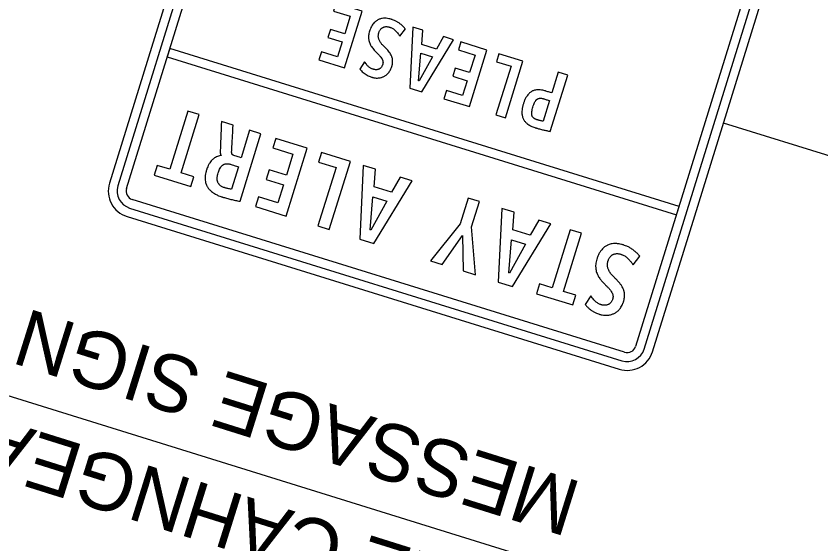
# Model space of a CAD drawing. Extents: x 2135767 to 2151731, y 141839 to 175894.
# Drawn here: x 2151050.4 to 2151135.3, y 149117.3 to 149173 of the extents above; entities that cross this region are included whole.
import ezdxf

# ---------------------------------------------------------------- set-up
doc = ezdxf.new("R2010")
doc.units = 0
for name, color, linetype in [('PR_Dimensions_Phase', 7, 'Continuous'), ('PR_Traffic_Control_Devices_Temp', 7, 'Continuous'), ('PR_Txt', 7, 'Continuous')]:
    doc.layers.add(name, color=color, linetype=linetype)

msp = doc.modelspace()

# ---------------------------------------------------------------- linework, layer by layer
at = {"layer": 'PR_Dimensions_Phase'}
for p, q in [((2151325.291, 149099.595), (2151125.02, 149161.695)), ((2151310.484, 149051.853), (2151016.595, 149143.158))]:
    msp.add_line(p, q, dxfattribs=at)
at = {"layer": 'PR_Traffic_Control_Devices_Temp'}
for p, q in [((2151090.863, 149170.866), (2151091.446, 149171.627)), ((2151087.144, 149168.154), (2151086.651, 149167.385)), ((2151106.656, 149164.065), (2151105.981, 149161.889)), ((2151073.274, 149161.472), (2151072.029, 149161.858)), ((2151072.014, 149158.28), (2151072.01, 149158.266)), ((2151073.822, 149157.085), (2151073.085, 149154.709)), ((2151115.495, 149146.724), (2151116.194, 149147.637)), ((2151111.032, 149143.47), (2151110.44, 149142.547))]:
    msp.add_line(p, q, dxfattribs=at)
for points in [[(2151076.329, 149207.298), (2151064.664, 149169.678), (2151060.221, 149155.351)], [(2151077.225, 149207.02), (2151061.116, 149155.073)], [(2151062.012, 149154.795), (2151078.12, 149206.743)], [(2151131.858, 149190.079), (2151115.75, 149138.132)], [(2151116.645, 149137.854), (2151132.754, 149189.801)], [(2151117.541, 149137.576), (2151121.983, 149151.903), (2151133.649, 149189.524)], [(2151084.294, 149168.677), (2151082.596, 149169.204), (2151082.331, 149168.348), (2151085.022, 149167.513), (2151086.873, 149173.483), (2151084.123, 149174.336), (2151083.864, 149173.502), (2151085.621, 149172.957), (2151085.047, 149171.107), (2151083.531, 149171.577), (2151083.266, 149170.722), (2151084.782, 149170.251), (2151084.294, 149168.677)], [(2151096.531, 149170.488), (2151095.487, 149170.812), (2151094.718, 149169.492), (2151093.203, 149169.962), (2151093.304, 149171.489), (2151092.23, 149171.822), (2151091.914, 149165.36), (2151093.172, 149164.97), (2151096.531, 149170.488)], [(2151097.969, 149166.162), (2151097.48, 149164.588), (2151095.783, 149165.115), (2151095.518, 149164.259), (2151098.209, 149163.424), (2151100.06, 149169.394), (2151097.31, 149170.247), (2151097.051, 149169.413), (2151098.807, 149168.868), (2151098.234, 149167.018), (2151096.718, 149167.488), (2151096.453, 149166.632), (2151097.969, 149166.162)], [(2151093.075, 149169.063), (2151094.298, 149168.684), (2151092.896, 149166.145), (2151092.836, 149166.164), (2151093.075, 149169.063)], [(2151103.857, 149168.217), (2151101.318, 149169.004), (2151101.057, 149168.162), (2151102.602, 149167.683), (2151101.012, 149162.555), (2151102.005, 149162.247), (2151103.857, 149168.217)], [(2151106.737, 149160.814), (2151108.578, 149166.752), (2151107.585, 149167.061), (2151106.905, 149164.87)], [(2151069.69, 149162.583), (2151068.498, 149162.953), (2151066.595, 149156.816), (2151065.27, 149157.227), (2151064.952, 149156.2), (2151068.793, 149155.009), (2151069.112, 149156.036), (2151067.787, 149156.447), (2151069.69, 149162.583)], [(2151073.998, 149153.437), (2151076.207, 149160.562), (2151075.015, 149160.932), (2151074.119, 149158.042)], [(2151081.086, 149159.049), (2151077.785, 149160.073), (2151077.475, 149159.072), (2151079.583, 149158.418), (2151078.895, 149156.199), (2151077.076, 149156.763), (2151076.757, 149155.736), (2151078.576, 149155.172), (2151077.99, 149153.283), (2151075.954, 149153.914), (2151075.635, 149152.887), (2151078.864, 149151.886), (2151081.086, 149159.049)], [(2151082.228, 149150.843), (2151083.42, 149150.473), (2151085.642, 149157.637), (2151082.595, 149158.581), (2151082.282, 149157.572), (2151084.136, 149156.997), (2151082.228, 149150.843)], [(2151092.167, 149155.613), (2151090.914, 149156.002), (2151089.991, 149154.418), (2151088.173, 149154.982), (2151088.294, 149156.814), (2151087.006, 149157.214), (2151086.626, 149149.46), (2151088.136, 149148.992), (2151092.167, 149155.613)], [(2151114.577, 149137.514), (2151062.63, 149153.622)], [(2151088.019, 149153.904), (2151089.487, 149153.448), (2151087.805, 149150.402), (2151087.733, 149150.424), (2151088.019, 149153.904)], [(2151097.496, 149149.815), (2151097.563, 149146.088), (2151098.837, 149145.693), (2151098.438, 149150.732), (2151099.269, 149153.411), (2151098.076, 149153.781), (2151097.23, 149151.052), (2151094.108, 149147.159), (2151095.332, 149146.78), (2151097.496, 149149.815)], [(2151062.352, 149152.727), (2151114.299, 149136.619)], [(2151106.795, 149151.077), (2151105.542, 149151.466), (2151104.619, 149149.882), (2151102.801, 149150.446), (2151102.922, 149152.278), (2151101.633, 149152.678), (2151101.254, 149144.924), (2151102.764, 149144.456), (2151106.795, 149151.077)], [(2151062.074, 149151.831), (2151114.021, 149135.723)], [(2151110.028, 149150.075), (2151108.835, 149150.445), (2151106.933, 149144.308), (2151105.608, 149144.719), (2151105.29, 149143.692), (2151109.131, 149142.501), (2151109.45, 149143.528), (2151108.125, 149143.938), (2151110.028, 149150.075)], [(2151102.647, 149149.368), (2151104.115, 149148.913), (2151102.432, 149145.866), (2151102.361, 149145.888), (2151102.647, 149149.368)]]:
    msp.add_lwpolyline(points, dxfattribs=at)
msp.add_lwpolyline([(2151120.054, 149152.011), (2151120.331, 149152.907), (2151066.593, 149169.57), (2151066.316, 149168.675)], close=True, dxfattribs=at)
msp.add_lwpolyline([(2151120.054, 149152.011), (2151120.331, 149152.907), (2151066.593, 149169.57), (2151066.316, 149168.675)], close=True, dxfattribs=at)
for centre, radius, start, end in [((2151062.907, 149154.518), 2.812, 162.77193, 252.77193), ((2151062.907, 149154.518), 1.875, 162.77193, 252.77193), ((2151062.907, 149154.518), 0.937, 162.77193, 252.77193), ((2151114.854, 149138.409), 0.937, 252.77193, 342.77193), ((2151114.854, 149138.409), 2.812, 252.77193, 342.77193), ((2151114.854, 149138.409), 1.875, 252.77193, 342.77193)]:
    msp.add_arc(centre, radius, start, end, dxfattribs=at)
for points in [[(2151091.446, 149171.627), (2151091.399, 149171.682), (2151091.259, 149171.846), (2151091.047, 149172.043), (2151090.82, 149172.223), (2151090.573, 149172.389), (2151090.297, 149172.525), (2151090.078, 149172.599), (2151090.002, 149172.624), (2151089.929, 149172.645), (2151089.722, 149172.705), (2151089.414, 149172.752), (2151089.12, 149172.748), (2151088.91, 149172.715), (2151088.741, 149172.667), (2151088.609, 149172.61), (2151088.508, 149172.555), (2151088.411, 149172.494), (2151088.296, 149172.408), (2151088.169, 149172.29), (2151088.032, 149172.133), (2151087.874, 149171.899), (2151087.749, 149171.633), (2151087.687, 149171.441), (2151087.665, 149171.374)], [(2151086.651, 149167.385), (2151086.692, 149167.336), (2151086.814, 149167.191), (2151086.997, 149167.018), (2151087.193, 149166.868), (2151087.406, 149166.731), (2151087.643, 149166.619), (2151087.832, 149166.556), (2151087.898, 149166.534), (2151087.956, 149166.518), (2151088.123, 149166.47), (2151088.378, 149166.437), (2151088.628, 149166.446), (2151088.815, 149166.477), (2151088.945, 149166.513), (2151089.072, 149166.56), (2151089.173, 149166.605), (2151089.293, 149166.67), (2151089.407, 149166.744), (2151089.533, 149166.846), (2151089.648, 149166.961), (2151089.733, 149167.067), (2151089.843, 149167.229), (2151089.937, 149167.412), (2151089.993, 149167.578), (2151090.012, 149167.636), (2151090.025, 149167.678), (2151090.06, 149167.8), (2151090.097, 149168.003), (2151090.109, 149168.243), (2151090.089, 149168.437), (2151090.061, 149168.569), (2151090.039, 149168.644), (2151089.998, 149168.764), (2151089.904, 149168.954), (2151089.763, 149169.159), (2151089.583, 149169.383), (2151089.455, 149169.516), (2151089.368, 149169.607), (2151089.152, 149169.819), (2151088.922, 149170.045), (2151088.734, 149170.347), (2151088.68, 149170.46), (2151088.634, 149170.595), (2151088.607, 149170.717), (2151088.594, 149170.808), (2151088.591, 149170.905), (2151088.601, 149171.005), (2151088.62, 149171.11), (2151088.638, 149171.174), (2151088.65, 149171.218), (2151088.661, 149171.25), (2151088.692, 149171.342), (2151088.755, 149171.47), (2151088.834, 149171.581), (2151088.903, 149171.655), (2151088.968, 149171.71), (2151089.026, 149171.749), (2151089.075, 149171.777), (2151089.126, 149171.802), (2151089.191, 149171.828), (2151089.273, 149171.85), (2151089.373, 149171.865), (2151089.51, 149171.868), (2151089.65, 149171.848), (2151089.744, 149171.821), (2151089.776, 149171.811), (2151089.807, 149171.801), (2151089.896, 149171.772), (2151090.038, 149171.709), (2151090.196, 149171.615), (2151090.316, 149171.521), (2151090.425, 149171.417), (2151090.529, 149171.305), (2151090.688, 149171.119), (2151090.793, 149170.967), (2151090.863, 149170.866)], [(2151087.665, 149171.374), (2151087.645, 149171.305), (2151087.599, 149171.144), (2151087.563, 149170.918), (2151087.556, 149170.733), (2151087.565, 149170.59), (2151087.59, 149170.405), (2151087.642, 149170.2), (2151087.721, 149170.012), (2151087.812, 149169.835), (2151087.92, 149169.67), (2151088.075, 149169.483), (2151088.236, 149169.306), (2151088.368, 149169.169), (2151088.432, 149169.102), (2151088.497, 149169.039), (2151088.687, 149168.854), (2151088.881, 149168.633), (2151088.998, 149168.438), (2151089.037, 149168.36), (2151089.065, 149168.28), (2151089.082, 149168.2), (2151089.09, 149168.131), (2151089.09, 149168.062), (2151089.084, 149168.004), (2151089.073, 149167.946), (2151089.063, 149167.911), (2151089.057, 149167.888), (2151089.047, 149167.857), (2151089.014, 149167.758), (2151088.953, 149167.639), (2151088.876, 149167.541), (2151088.822, 149167.485), (2151088.763, 149167.438), (2151088.71, 149167.406), (2151088.654, 149167.379), (2151088.574, 149167.348), (2151088.452, 149167.32), (2151088.299, 149167.316), (2151088.169, 149167.335), (2151088.091, 149167.357), (2151088.064, 149167.365), (2151088.039, 149167.374), (2151087.964, 149167.398), (2151087.846, 149167.449), (2151087.715, 149167.523), (2151087.616, 149167.595), (2151087.525, 149167.677), (2151087.4, 149167.806), (2151087.266, 149167.971), (2151087.176, 149168.107), (2151087.144, 149168.154)], [(2151106.905, 149164.87), (2151106.691, 149164.937), (2151106.476, 149165.003), (2151106.261, 149165.07), (2151106.187, 149165.091), (2151105.978, 149165.152), (2151105.668, 149165.203), (2151105.373, 149165.204), (2151105.165, 149165.175), (2151104.999, 149165.13), (2151104.87, 149165.077), (2151104.773, 149165.025), (2151104.678, 149164.966), (2151104.565, 149164.879), (2151104.438, 149164.755), (2151104.299, 149164.583), (2151104.134, 149164.319), (2151103.998, 149164.014), (2151103.926, 149163.794), (2151103.9, 149163.715)], [(2151104.91, 149163.383), (2151104.94, 149163.477), (2151104.996, 149163.648), (2151105.086, 149163.864), (2151105.168, 149164.011), (2151105.237, 149164.103), (2151105.29, 149164.159), (2151105.335, 149164.197), (2151105.38, 149164.23), (2151105.441, 149164.264), (2151105.52, 149164.293), (2151105.591, 149164.307), (2151105.649, 149164.312), (2151105.712, 149164.314), (2151105.817, 149164.306), (2151105.948, 149164.282), (2151106.043, 149164.254), (2151106.084, 149164.242), (2151106.275, 149164.183), (2151106.465, 149164.124), (2151106.656, 149164.065)], [(2151103.9, 149163.715), (2151103.875, 149163.631), (2151103.806, 149163.394), (2151103.753, 149163.081), (2151103.745, 149162.818), (2151103.753, 149162.65), (2151103.774, 149162.492), (2151103.819, 149162.312), (2151103.874, 149162.172), (2151103.928, 149162.067), (2151103.988, 149161.967), (2151104.076, 149161.849), (2151104.201, 149161.718), (2151104.319, 149161.62), (2151104.45, 149161.528), (2151104.656, 149161.404), (2151104.917, 149161.286), (2151105.126, 149161.217), (2151105.199, 149161.193), (2151105.272, 149161.171), (2151105.412, 149161.128), (2151105.617, 149161.069), (2151105.812, 149161.017), (2151105.999, 149160.971), (2151106.182, 149160.928), (2151106.365, 149160.89), (2151106.55, 149160.853), (2151106.674, 149160.827), (2151106.737, 149160.814)], [(2151105.981, 149161.889), (2151105.926, 149161.901), (2151105.818, 149161.926), (2151105.659, 149161.958), (2151105.509, 149161.99), (2151105.413, 149162.018), (2151105.366, 149162.032), (2151105.329, 149162.044), (2151105.243, 149162.073), (2151105.131, 149162.123), (2151105.048, 149162.174), (2151105, 149162.21), (2151104.958, 149162.247), (2151104.91, 149162.297), (2151104.863, 149162.364), (2151104.833, 149162.425), (2151104.815, 149162.478), (2151104.799, 149162.533), (2151104.782, 149162.625), (2151104.779, 149162.74), (2151104.793, 149162.907), (2151104.833, 149163.119), (2151104.883, 149163.29), (2151104.91, 149163.383)], [(2151072.029, 149161.858), (2151071.991, 149160.801), (2151071.952, 149159.744), (2151071.914, 149158.687), (2151071.914, 149158.645), (2151071.914, 149158.563), (2151071.923, 149158.473), (2151071.934, 149158.409), (2151071.945, 149158.373), (2151071.961, 149158.341), (2151071.975, 149158.318), (2151071.99, 149158.301), (2151072.003, 149158.289), (2151072.011, 149158.282), (2151072.014, 149158.28)], [(2151074.119, 149158.042), (2151073.85, 149158.126), (2151073.581, 149158.209), (2151073.313, 149158.292), (2151073.301, 149158.296), (2151073.274, 149158.305), (2151073.24, 149158.322), (2151073.209, 149158.341), (2151073.188, 149158.36), (2151073.169, 149158.38), (2151073.154, 149158.403), (2151073.145, 149158.423), (2151073.138, 149158.445), (2151073.132, 149158.468), (2151073.119, 149158.538), (2151073.114, 149158.631), (2151073.116, 149158.714), (2151073.117, 149158.745), (2151073.169, 149159.654), (2151073.222, 149160.563), (2151073.274, 149161.472)], [(2151072.01, 149158.266), (2151071.967, 149158.26), (2151071.842, 149158.242), (2151071.638, 149158.184), (2151071.406, 149158.077), (2151071.227, 149157.956), (2151071.092, 149157.843), (2151070.957, 149157.71), (2151070.803, 149157.509), (2151070.644, 149157.223), (2151070.53, 149156.951), (2151070.473, 149156.775), (2151070.453, 149156.713), (2151070.429, 149156.627), (2151070.349, 149156.349), (2151070.302, 149155.984), (2151070.323, 149155.639), (2151070.361, 149155.429), (2151070.424, 149155.229), (2151070.496, 149155.071), (2151070.565, 149154.952), (2151070.642, 149154.836), (2151070.752, 149154.697), (2151070.878, 149154.569), (2151071.077, 149154.396), (2151071.381, 149154.193), (2151071.765, 149154.018), (2151072.017, 149153.935), (2151072.106, 149153.905), (2151072.188, 149153.88), (2151072.347, 149153.832), (2151072.584, 149153.764), (2151072.815, 149153.702), (2151073.043, 149153.642), (2151073.27, 149153.586), (2151073.503, 149153.535), (2151073.746, 149153.485), (2151073.912, 149153.453), (2151073.998, 149153.437)], [(2151071.692, 149156.43), (2151071.708, 149156.482), (2151071.755, 149156.626), (2151071.846, 149156.843), (2151071.964, 149157.046), (2151072.073, 149157.178), (2151072.15, 149157.247), (2151072.202, 149157.284), (2151072.255, 149157.317), (2151072.325, 149157.351), (2151072.415, 149157.38), (2151072.511, 149157.398), (2151072.594, 149157.403), (2151072.722, 149157.401), (2151072.857, 149157.381), (2151072.97, 149157.348), (2151073.01, 149157.336), (2151073.281, 149157.253), (2151073.551, 149157.169), (2151073.822, 149157.085)], [(2151073.085, 149154.709), (2151073.023, 149154.718), (2151072.901, 149154.736), (2151072.721, 149154.775), (2151072.547, 149154.82), (2151072.434, 149154.854), (2151072.378, 149154.87), (2151072.326, 149154.888), (2151072.203, 149154.929), (2151072.046, 149155.006), (2151071.933, 149155.085), (2151071.87, 149155.141), (2151071.815, 149155.198), (2151071.753, 149155.271), (2151071.693, 149155.365), (2151071.654, 149155.448), (2151071.63, 149155.516), (2151071.61, 149155.585), (2151071.592, 149155.675), (2151071.585, 149155.766), (2151071.584, 149155.861), (2151071.594, 149155.998), (2151071.626, 149156.196), (2151071.67, 149156.352), (2151071.692, 149156.43)], [(2151116.194, 149147.637), (2151116.138, 149147.703), (2151115.969, 149147.9), (2151115.716, 149148.137), (2151115.443, 149148.353), (2151115.146, 149148.552), (2151114.816, 149148.715), (2151114.552, 149148.803), (2151114.462, 149148.834), (2151114.374, 149148.859), (2151114.126, 149148.931), (2151113.756, 149148.987), (2151113.403, 149148.983), (2151113.151, 149148.943), (2151112.948, 149148.885), (2151112.789, 149148.817), (2151112.669, 149148.751), (2151112.553, 149148.678), (2151112.414, 149148.575), (2151112.262, 149148.433), (2151112.097, 149148.245), (2151111.908, 149147.964), (2151111.758, 149147.644), (2151111.683, 149147.414), (2151111.657, 149147.333)], [(2151110.44, 149142.547), (2151110.49, 149142.488), (2151110.635, 149142.314), (2151110.855, 149142.107), (2151111.091, 149141.926), (2151111.346, 149141.762), (2151111.631, 149141.627), (2151111.858, 149141.552), (2151111.936, 149141.526), (2151112.006, 149141.506), (2151112.207, 149141.449), (2151112.513, 149141.409), (2151112.813, 149141.42), (2151113.037, 149141.458), (2151113.193, 149141.501), (2151113.346, 149141.556), (2151113.466, 149141.61), (2151113.611, 149141.689), (2151113.748, 149141.777), (2151113.899, 149141.899), (2151114.036, 149142.038), (2151114.138, 149142.165), (2151114.271, 149142.36), (2151114.384, 149142.579), (2151114.451, 149142.779), (2151114.474, 149142.848), (2151114.489, 149142.898), (2151114.531, 149143.044), (2151114.575, 149143.288), (2151114.59, 149143.576), (2151114.566, 149143.809), (2151114.532, 149143.967), (2151114.506, 149144.057), (2151114.456, 149144.202), (2151114.343, 149144.43), (2151114.174, 149144.676), (2151113.959, 149144.944), (2151113.806, 149145.103), (2151113.7, 149145.213), (2151113.441, 149145.467), (2151113.165, 149145.739), (2151112.94, 149146.101), (2151112.875, 149146.237), (2151112.82, 149146.398), (2151112.787, 149146.545), (2151112.772, 149146.655), (2151112.768, 149146.771), (2151112.78, 149146.891), (2151112.803, 149147.017), (2151112.825, 149147.094), (2151112.839, 149147.146), (2151112.852, 149147.185), (2151112.889, 149147.296), (2151112.965, 149147.449), (2151113.06, 149147.582), (2151113.143, 149147.67), (2151113.22, 149147.737), (2151113.29, 149147.784), (2151113.349, 149147.817), (2151113.41, 149147.847), (2151113.489, 149147.878), (2151113.587, 149147.905), (2151113.707, 149147.923), (2151113.871, 149147.926), (2151114.039, 149147.902), (2151114.152, 149147.87), (2151114.191, 149147.859), (2151114.227, 149147.847), (2151114.335, 149147.811), (2151114.505, 149147.736), (2151114.695, 149147.623), (2151114.838, 149147.51), (2151114.969, 149147.385), (2151115.094, 149147.251), (2151115.285, 149147.027), (2151115.411, 149146.845), (2151115.495, 149146.724)], [(2151111.657, 149147.333), (2151111.633, 149147.251), (2151111.578, 149147.057), (2151111.534, 149146.786), (2151111.527, 149146.564), (2151111.538, 149146.393), (2151111.567, 149146.17), (2151111.63, 149145.925), (2151111.725, 149145.699), (2151111.834, 149145.487), (2151111.963, 149145.288), (2151112.149, 149145.064), (2151112.342, 149144.852), (2151112.5, 149144.688), (2151112.578, 149144.607), (2151112.656, 149144.532), (2151112.884, 149144.31), (2151113.117, 149144.044), (2151113.257, 149143.811), (2151113.303, 149143.716), (2151113.337, 149143.621), (2151113.358, 149143.525), (2151113.367, 149143.442), (2151113.367, 149143.359), (2151113.359, 149143.29), (2151113.347, 149143.22), (2151113.335, 149143.178), (2151113.327, 149143.15), (2151113.315, 149143.114), (2151113.275, 149142.994), (2151113.203, 149142.852), (2151113.111, 149142.733), (2151113.046, 149142.667), (2151112.975, 149142.611), (2151112.911, 149142.572), (2151112.844, 149142.54), (2151112.748, 149142.502), (2151112.602, 149142.469), (2151112.418, 149142.464), (2151112.262, 149142.487), (2151112.168, 149142.514), (2151112.136, 149142.523), (2151112.105, 149142.533), (2151112.016, 149142.562), (2151111.874, 149142.623), (2151111.717, 149142.712), (2151111.598, 149142.799), (2151111.489, 149142.897), (2151111.339, 149143.052), (2151111.178, 149143.25), (2151111.07, 149143.413), (2151111.032, 149143.47)]]:
    msp.add_open_spline(points, degree=3, dxfattribs=at)

# ---------------------------------------------------------------- texts
at = {"layer": 'PR_Txt'}
for s, p in [('MESSAGE SIGN', (2151110.246, 149123.746)), ('PORTABLE CAHNGEABLE', (2151128.368, 149105.48))]:
    msp.add_text(s, height=5.99999, rotation=162.57228, dxfattribs=at).set_placement(p)

doc.saveas('drawing.dxf')
